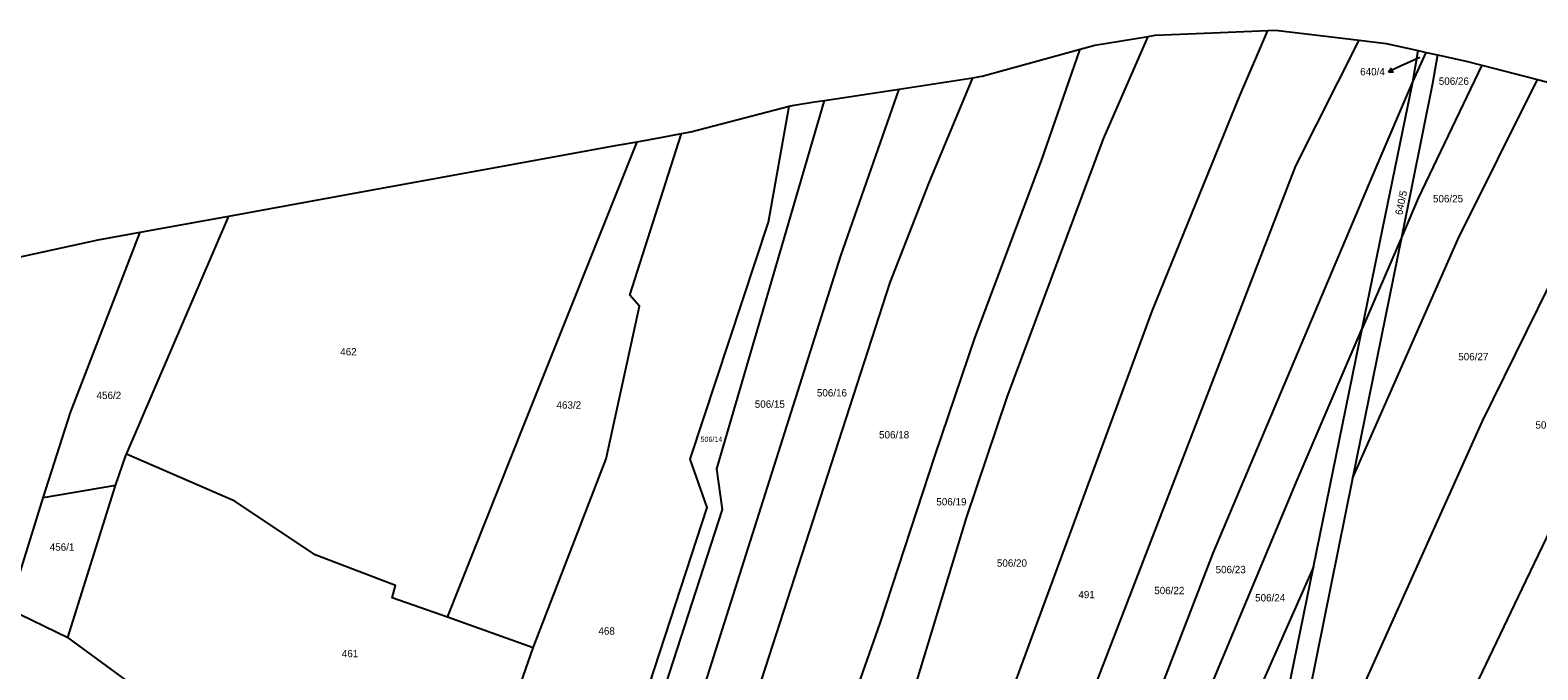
# Model space of a CAD drawing. Extents: x -744566 to -741843, y -1128407 to -1126744.
# Drawn here: x -742846.8 to -742498.8, y -1126915.6 to -1126767.8 of the extents above; entities that cross this region are included whole.
import ezdxf

# ---------------------------------------------------------------- set-up
doc = ezdxf.new("R2010")
doc.units = 0
for name, color, linetype in [('Hranice parcel', 7, 'Continuous'), ('Parcelní čísla', 7, 'Continuous'), ('Pop  PČ popisy', 7, 'Continuous')]:
    doc.layers.add(name, color=color, linetype=linetype)

msp = doc.modelspace()

# ---------------------------------------------------------------- linework, layer by layer
at = {"layer": 'Hranice parcel'}
for p, q in [((-742540.06, -1126770.15), (-742533.77, -1126770.91)), ((-742533.77, -1126770.91), (-742526.41, -1126772.54)), ((-742527.67, -1126779.74), (-742526.41, -1126772.54)), ((-742527.67, -1126779.74), (-742524.54, -1126772.95)), ((-742526.41, -1126772.54), (-742524.54, -1126772.95)), ((-742524.54, -1126772.95), (-742521.95, -1126773.52)), ((-742511.74, -1126775.91), (-742498.85, -1126779.22)), ((-742646.21, -1126781.41), (-742629.18, -1126778.81)), ((-742539.32, -1126836.74), (-742527.67, -1126779.74)), ((-742498.85, -1126779.22), (-742475.66, -1126785.18)), ((-742706.72, -1126793.58), (-742700.87, -1126792.51)), ((-742700.87, -1126792.51), (-742696.43, -1126791.7)), ((-742824.58, -1126865.74), (-742800.98, -1126810.76)), ((-742821.45, -1126814.49), (-742800.98, -1126810.76)), ((-742530.29, -1126815.68), (-742541.56, -1126871.36)), ((-742530.29, -1126815.68), (-742539.32, -1126836.74)), ((-742550.57, -1126891.8), (-742539.32, -1126836.74)), ((-742827.15, -1126873), (-742843.85, -1126875.84)), ((-742838.1, -1126908.15), (-742827.15, -1126873)), ((-742851.71, -1126901.51), (-742843.85, -1126875.84)), ((-742851.71, -1126901.51), (-742838.1, -1126908.15)), ((-742730.7, -1126910.48), (-742750.49, -1126903.46)), ((-742810.76, -1126928.12), (-742838.1, -1126908.15)), ((-742741.76, -1126942.06), (-742730.7, -1126910.48))]:
    msp.add_line(p, q, dxfattribs=at)
for points in [[(-742679.87, -1127010.3), (-742661.43, -1126968.75), (-742645.29, -1126928.59), (-742630.66, -1126880.5), (-742621.29, -1126852.62), (-742599.04, -1126792.93), (-742588.76, -1126769.25)], [(-742561.23, -1126767.89), (-742567.77, -1126783.13), (-742587.89, -1126832.72), (-742634.42, -1126959.12), (-742661.75, -1127022.4)], [(-742648.95, -1127033.28), (-742621.1, -1126971.78), (-742603.91, -1126926.94), (-742554.63, -1126799.18), (-742540.06, -1126770.15)], [(-742604.44, -1126772.24), (-742601.05, -1126771.3), (-742588.76, -1126769.25)], [(-742588.76, -1126769.25), (-742587.09, -1126768.97), (-742573.9, -1126768.42), (-742561.23, -1126767.89)], [(-742561.23, -1126767.89), (-742559.37, -1126767.81), (-742540.06, -1126770.15)], [(-742688.81, -1127002.53), (-742675.39, -1126975.35), (-742650.59, -1126904.79), (-742637.92, -1126865.97), (-742628.71, -1126838.73), (-742613.44, -1126798.13), (-742604.44, -1126772.24)], [(-742629.18, -1126778.81), (-742627.56, -1126778.56), (-742627.03, -1126778.48), (-742604.44, -1126772.24)], [(-742521.95, -1126773.52), (-742523.09, -1126780.11), (-742530.29, -1126815.68)], [(-742521.95, -1126773.52), (-742516.73, -1126774.67), (-742515.35, -1126774.98), (-742511.74, -1126775.91)], [(-742511.74, -1126775.91), (-742526.39, -1126806.59), (-742530.29, -1126815.68)], [(-742703.1, -1126987.76), (-742688.91, -1126951.77), (-742648.33, -1126826.13), (-742639.39, -1126803.22), (-742629.18, -1126778.81)], [(-742638.43, -1127039.61), (-742614.56, -1126990.57), (-742601.46, -1126960.43), (-742573.73, -1126888.65), (-742536.1, -1126799.53), (-742527.67, -1126779.74)], [(-742541.56, -1126871.36), (-742517.16, -1126816.01), (-742498.85, -1126779.22)], [(-742716.17, -1126970.68), (-742712.23, -1126956.56), (-742687.03, -1126878.58), (-742688.27, -1126869.14), (-742663.45, -1126784.04)], [(-742710.71, -1126977.95), (-742691.49, -1126920.27), (-742659.71, -1126819.94), (-742646.21, -1126781.41)], [(-742671.59, -1126785.41), (-742670.45, -1126785.11), (-742665.8, -1126784.4), (-742663.45, -1126784.04)], [(-742663.45, -1126784.04), (-742654.84, -1126782.73), (-742646.21, -1126781.41)], [(-742719.6, -1126967.23), (-742690.51, -1126878.08), (-742694.48, -1126866.91), (-742676.36, -1126812.17), (-742671.59, -1126785.41)], [(-742696.43, -1126791.7), (-742694.29, -1126791.31), (-742671.59, -1126785.41)], [(-742562.72, -1126972.14), (-742511.64, -1126858.28), (-742475.66, -1126785.18)], [(-742769.01, -1126804.93), (-742735.24, -1126798.77), (-742711.7, -1126794.48), (-742706.72, -1126793.58)], [(-742750.49, -1126903.46), (-742732.76, -1126858.93), (-742706.72, -1126793.58)], [(-742730.7, -1126910.48), (-742713.83, -1126866.81), (-742706.14, -1126831.54), (-742708.37, -1126829.06), (-742696.43, -1126791.7)], [(-742576.22, -1127042.62), (-742572.46, -1127037.81), (-742549.96, -1126996.44), (-742502.42, -1126896.85), (-742478.65, -1126847.35), (-742462.47, -1126810.41), (-742451.42, -1126791.4)], [(-742800.98, -1126810.76), (-742782.52, -1126807.39), (-742769.01, -1126804.93)], [(-742849.79, -1126820.34), (-742831.12, -1126816.25), (-742821.45, -1126814.49)], [(-742843.85, -1126875.84), (-742837.53, -1126856.16), (-742821.45, -1126814.49)], [(-742629.44, -1127044.36), (-742612.06, -1127010.59), (-742600.55, -1126985.29), (-742577.05, -1126926.06), (-742554.59, -1126872.35), (-742539.32, -1126836.74)], [(-742827.15, -1126873), (-742824.73, -1126866.08), (-742824.58, -1126865.74)], [(-742750.49, -1126903.46), (-742763.27, -1126898.97), (-742762.5, -1126896.14), (-742781.04, -1126889), (-742799.57, -1126876.62), (-742824.58, -1126865.74)], [(-742541.56, -1126871.36), (-742553.22, -1126928.98), (-742562.72, -1126972.14)], [(-742550.57, -1126891.8), (-742562.56, -1126918.99), (-742596.53, -1127002.73), (-742608.98, -1127027.64), (-742621.26, -1127048.47)], [(-742572.58, -1126993.14), (-742572.06, -1126989.56), (-742557.96, -1126927.95), (-742550.57, -1126891.8)]]:
    msp.add_lwpolyline(points, dxfattribs=at)
at = {"layer": 'Pop  PČ popisy'}
for p, q in [((-742530.52, -1126776.16), (-742533.24, -1126777.428)), ((-742533.24, -1126777.428), (-742532.544, -1126776.551)), ((-742526.01, -1126774.1), (-742530.52, -1126776.16)), ((-742533.24, -1126777.428), (-742532.121, -1126777.459))]:
    msp.add_line(p, q, dxfattribs=at)

# ---------------------------------------------------------------- texts
at = {"layer": 'Parcelní čísla'}
for s, height, p in [('640/4', 1.7, (-742539.796, -1126778.26)), ('506/26', 1.7, (-742521.65, -1126780.44)), ('506/25', 1.7, (-742522.99, -1126807.6)), ('462', 1.7, (-742775.24, -1126842.96)), ('506/27', 1.7, (-742517.16, -1126844.08)), ('456/2', 1.7, (-742831.49, -1126853.03)), ('463/2', 1.7, (-742725.32, -1126855.26)), ('506/15', 1.7, (-742679.55, -1126855.05)), ('506/16', 1.7, (-742665.21, -1126852.44)), ('506/18', 1.7, (-742650.86, -1126862.13)), ('506/28', 1.7, (-742499.34, -1126859.87)), ('506/14', 1.19, (-742692.07, -1126862.925)), ('506/19', 1.7, (-742637.63, -1126877.61)), ('456/1', 1.7, (-742842.3, -1126888.07)), ('506/20', 1.7, (-742623.66, -1126891.77)), ('506/23', 1.7, (-742573.17, -1126893.27)), ('491', 1.7, (-742604.85, -1126899.05)), ('506/22', 1.7, (-742587.33, -1126898.11)), ('506/24', 1.7, (-742564.05, -1126899.79)), ('468', 1.7, (-742715.64, -1126907.46)), ('461', 1.7, (-742774.87, -1126912.68))]:
    msp.add_text(s, height=height, dxfattribs=at).set_placement(p)
msp.add_text('640/5', height=1.7, rotation=78, dxfattribs=at).set_placement((-742530.108, -1126810.636))

doc.saveas('drawing.dxf')
